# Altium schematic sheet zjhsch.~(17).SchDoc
size A4
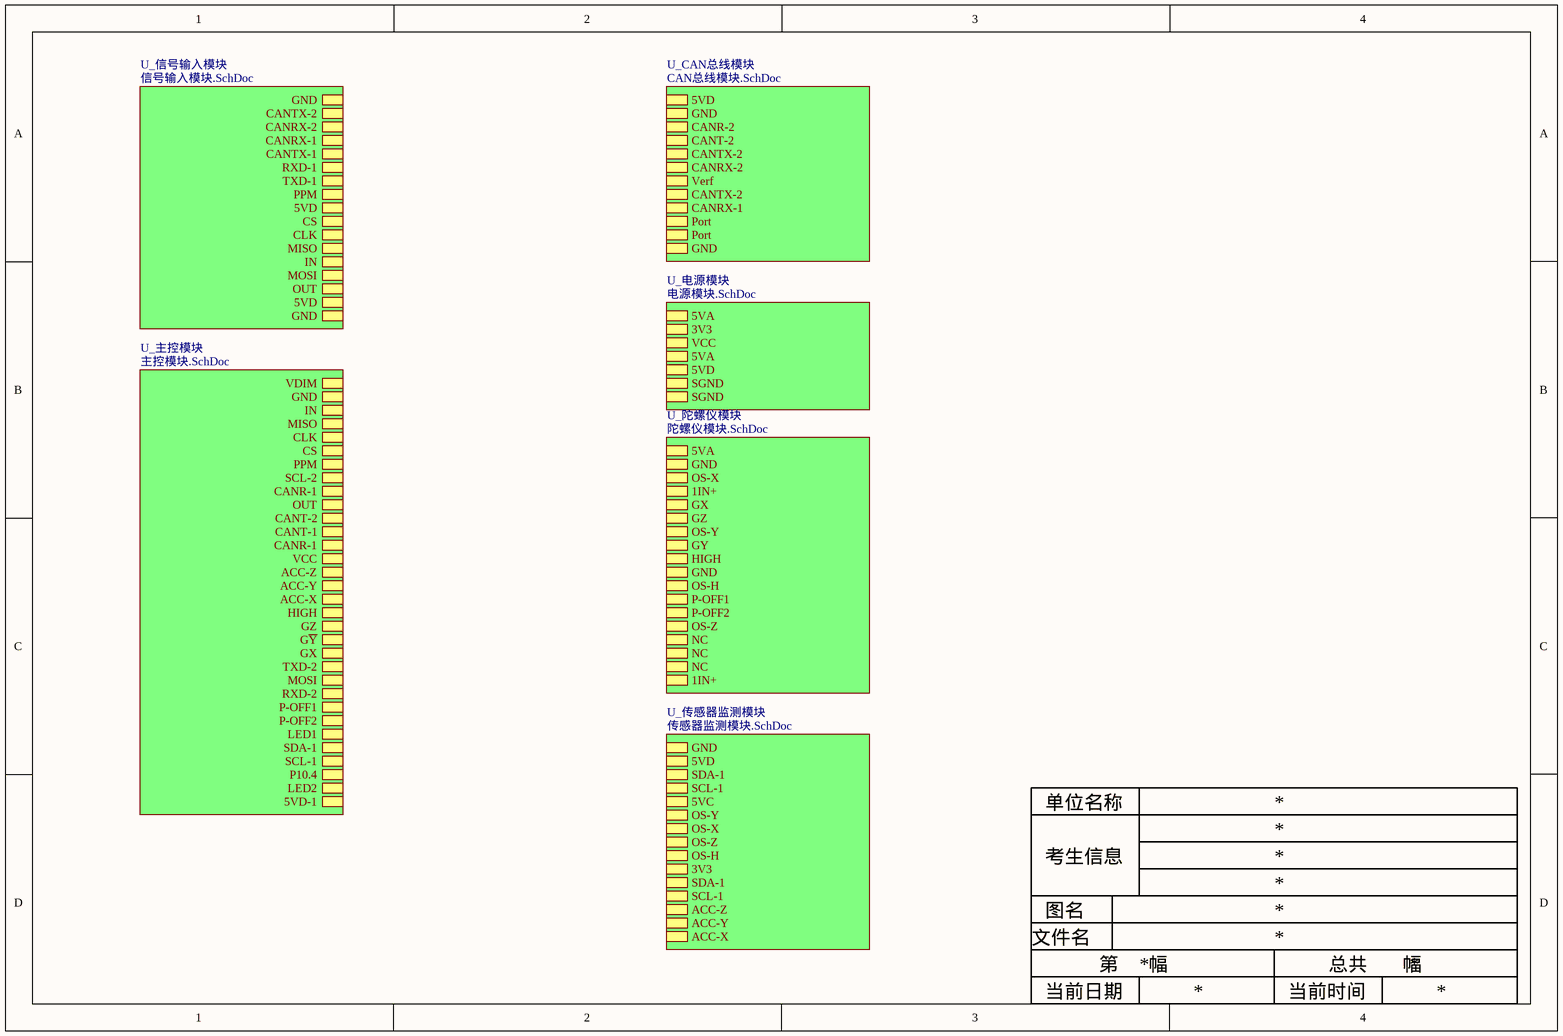
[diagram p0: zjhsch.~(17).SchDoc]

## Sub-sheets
U_CAN总线模块 = CAN总线模块.SchDoc: 5VD, GND, CANR-2, CANT-2, CANTX-2, CANRX-2, Verf, CANTX-2, CANRX-1, Port, Port, GND
U_主控模块 = 主控模块.SchDoc: 5VD-1, LED2, P10.4, SCL-1, SDA-1, LED1, P-OFF2, P-OFF1, RXD-2, MOSI, TXD-2, GX, G~{Y}, GZ, HIGH, ACC-X, ACC-Y, ACC-Z, VCC, CANR-1, CANT-1, CANT-2, OUT, CANR-1, SCL-2, PPM, CS, CLK, MISO, IN, GND, VDIM
U_传感器监测模块 = 传感器监测模块.SchDoc: GND, 5VD, SDA-1, SCL-1, 5VC, OS-Y, OS-X, OS-Z, OS-H, 3V3, SDA-1, SCL-1, ACC-Z, ACC-Y, ACC-X
U_信号输入模块 = 信号输入模块.SchDoc: GND, 5VD, OUT, MOSI, IN, MISO, CLK, CS, 5VD, PPM, TXD-1, RXD-1, CANTX-1, CANRX-1, CANRX-2, CANTX-2, GND
U_电源模块 = 电源模块.SchDoc: 5VA, 3V3, VCC, 5VA, 5VD, SGND, SGND
U_陀螺仪模块 = 陀螺仪模块.SchDoc: 5VA, GND, OS-X, 1IN+, GX, GZ, OS-Y, GY, HIGH, GND, OS-H, P-OFF1, P-OFF2, OS-Z, NC, NC, NC, 1IN+

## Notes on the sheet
- 单位名称
- 考生信息
- 图名
- 文件名
- 第      幅
- 总共       幅
- 当前日期
- 当前时间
